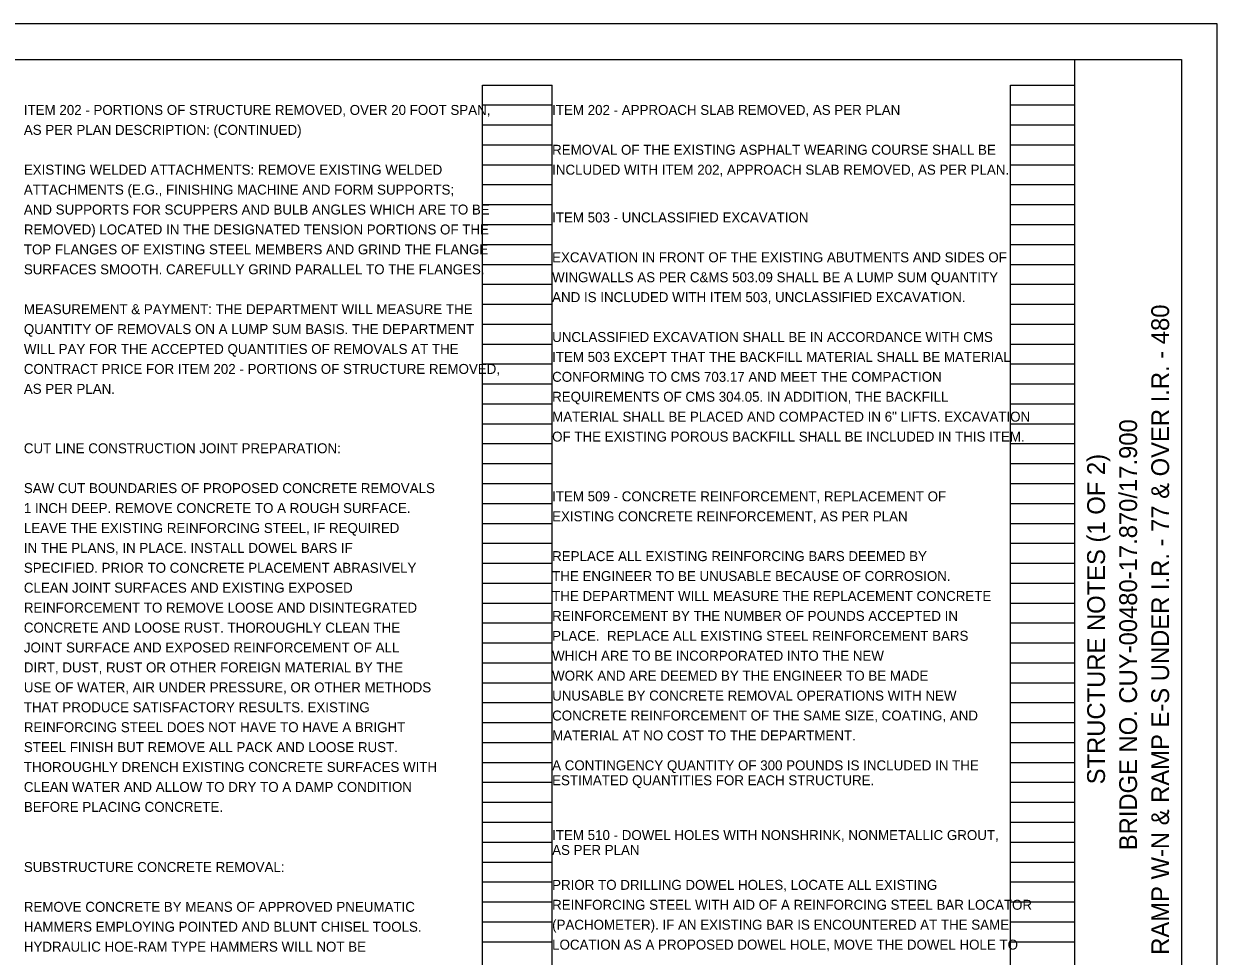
# Model space of a CAD drawing. Extents: x 0 to 34, y 0 to 22.
# Drawn here: x 17.24 to 34, y 8.9 to 22 of the extents above; entities that cross this region are included whole.
import ezdxf

# ---------------------------------------------------------------- set-up
doc = ezdxf.new("R2010")
doc.units = 0
for name, color, linetype in [('SH_Border', 7, 'Continuous'), ('SH_Cut_Line', 7, 'Continuous'), ('SH_Data', 7, 'Continuous'), ('SH_Text', 7, 'Continuous')]:
    doc.layers.add(name, color=color, linetype=linetype)

msp = doc.modelspace()

# ---------------------------------------------------------------- linework, layer by layer
at = {"layer": 'SH_Border'}
msp.add_line((32, 0.5), (32, 21.5), dxfattribs=at)
msp.add_lwpolyline([(1.5, 21.5), (33.5, 21.5), (33.5, 0.5), (1.5, 0.5)], close=True, dxfattribs=at)
at = {"layer": 'SH_Cut_Line'}
msp.add_lwpolyline([(0, 0), (34, 0), (34, 22), (0, 22)], close=True, dxfattribs=at)
at = {"layer": 'SH_Data'}
for p, q in [((23.68, 0.98), (23.68, 21.14)), ((23.68, 21.14), (24.66, 21.14)), ((24.66, 0.98), (24.66, 21.14)), ((31.1, 0.98), (31.1, 21.14)), ((31.1, 21.14), (32, 21.14)), ((32, 0.98), (32, 21.14)), ((23.68, 20.86), (24.66, 20.86)), ((31.1, 20.86), (32, 20.86)), ((23.68, 20.58), (24.66, 20.58)), ((31.1, 20.58), (32, 20.58)), ((23.68, 20.3), (24.66, 20.3)), ((31.1, 20.3), (32, 20.3)), ((23.68, 20.02), (24.66, 20.02)), ((31.1, 20.02), (32, 20.02)), ((23.68, 19.74), (24.66, 19.74)), ((31.1, 19.74), (32, 19.74)), ((23.68, 19.46), (24.66, 19.46)), ((31.1, 19.46), (32, 19.46)), ((23.68, 19.18), (24.66, 19.18)), ((31.1, 19.18), (32, 19.18)), ((23.68, 18.9), (24.66, 18.9)), ((31.1, 18.9), (32, 18.9)), ((23.68, 18.62), (24.66, 18.62)), ((31.1, 18.62), (32, 18.62)), ((23.68, 18.34), (24.66, 18.34)), ((31.1, 18.34), (32, 18.34)), ((23.68, 18.06), (24.66, 18.06)), ((31.1, 18.06), (32, 18.06)), ((23.68, 17.78), (24.66, 17.78)), ((31.1, 17.78), (32, 17.78)), ((23.68, 17.5), (24.66, 17.5)), ((31.1, 17.5), (32, 17.5)), ((23.68, 17.22), (24.66, 17.22)), ((31.1, 17.22), (32, 17.22)), ((23.68, 16.94), (24.66, 16.94)), ((31.1, 16.94), (32, 16.94)), ((23.68, 16.66), (24.66, 16.66)), ((31.1, 16.66), (32, 16.66)), ((23.68, 16.38), (24.66, 16.38)), ((31.1, 16.38), (32, 16.38)), ((23.68, 16.1), (24.66, 16.1)), ((31.1, 16.1), (32, 16.1)), ((23.68, 15.82), (24.66, 15.82)), ((31.1, 15.82), (32, 15.82)), ((23.68, 15.54), (24.66, 15.54)), ((31.1, 15.54), (32, 15.54)), ((23.68, 15.26), (24.66, 15.26)), ((31.1, 15.26), (32, 15.26)), ((23.68, 14.98), (24.66, 14.98)), ((31.1, 14.98), (32, 14.98)), ((23.68, 14.7), (24.66, 14.7)), ((31.1, 14.7), (32, 14.7)), ((23.68, 14.42), (24.66, 14.42)), ((31.1, 14.42), (32, 14.42)), ((23.68, 14.14), (24.66, 14.14)), ((31.1, 14.14), (32, 14.14)), ((23.68, 13.86), (24.66, 13.86)), ((31.1, 13.86), (32, 13.86)), ((23.68, 13.58), (24.66, 13.58)), ((31.1, 13.58), (32, 13.58)), ((23.68, 13.3), (24.66, 13.3)), ((31.1, 13.3), (32, 13.3)), ((23.68, 13.02), (24.66, 13.02)), ((31.1, 13.02), (32, 13.02)), ((23.68, 12.74), (24.66, 12.74)), ((31.1, 12.74), (32, 12.74)), ((23.68, 12.46), (24.66, 12.46)), ((31.1, 12.46), (32, 12.46)), ((23.68, 12.18), (24.66, 12.18)), ((31.1, 12.18), (32, 12.18)), ((23.68, 11.9), (24.66, 11.9)), ((31.1, 11.9), (32, 11.9)), ((23.68, 11.62), (24.66, 11.62)), ((31.1, 11.62), (32, 11.62)), ((23.68, 11.34), (24.66, 11.34)), ((31.1, 11.34), (32, 11.34)), ((23.68, 11.06), (24.66, 11.06)), ((31.1, 11.06), (32, 11.06)), ((23.68, 10.78), (24.66, 10.78)), ((31.1, 10.78), (32, 10.78)), ((23.68, 10.5), (24.66, 10.5)), ((31.1, 10.5), (32, 10.5)), ((23.68, 10.22), (24.66, 10.22)), ((31.1, 10.22), (32, 10.22)), ((23.68, 9.94), (24.66, 9.94)), ((31.1, 9.94), (32, 9.94)), ((23.68, 9.66), (24.66, 9.66)), ((31.1, 9.66), (32, 9.66)), ((23.68, 9.38), (24.66, 9.38)), ((31.1, 9.38), (32, 9.38)), ((23.68, 9.1), (24.66, 9.1)), ((31.1, 9.1), (32, 9.1))]:
    msp.add_line(p, q, dxfattribs=at)

# ---------------------------------------------------------------- texts
for s, p in [('RAMP W-N & RAMP E-S UNDER I.R. - 77 & OVER I.R. - 480', (33.325, 8.916)), ('BRIDGE NO. CUY-00480-17.870/17.900', (32.875, 10.385)), ('STRUCTURE NOTES (1 OF 2)', (32.425, 11.312))]:
    msp.add_text(s, height=0.25, rotation=90, dxfattribs=at).set_placement(p)
at = {"layer": 'SH_Text'}
for s, p in [('ITEM 202 - PORTIONS OF STRUCTURE REMOVED, OVER 20 FOOT SPAN,', (17.24, 20.72)), ('ITEM 202 - APPROACH SLAB REMOVED, AS PER PLAN', (24.66, 20.72)), ('AS PER PLAN DESCRIPTION: (CONTINUED)', (17.24, 20.44)), ('REMOVAL OF THE EXISTING ASPHALT WEARING COURSE SHALL BE', (24.66, 20.16)), ('EXISTING WELDED ATTACHMENTS: REMOVE EXISTING WELDED', (17.24, 19.88)), ('INCLUDED WITH ITEM 202, APPROACH SLAB REMOVED, AS PER PLAN.', (24.66, 19.88)), ('ATTACHMENTS (E.G., FINISHING MACHINE AND FORM SUPPORTS;', (17.24, 19.6)), ('AND SUPPORTS FOR SCUPPERS AND BULB ANGLES WHICH ARE TO BE', (17.24, 19.32)), ('ITEM 503 - UNCLASSIFIED EXCAVATION', (24.66, 19.209)), ('REMOVED) LOCATED IN THE DESIGNATED TENSION PORTIONS OF THE', (17.24, 19.04)), ('TOP FLANGES OF EXISTING STEEL MEMBERS AND GRIND THE FLANGE', (17.24, 18.76)), ('EXCAVATION IN FRONT OF THE EXISTING ABUTMENTS AND SIDES OF ', (24.66, 18.649)), ('SURFACES SMOOTH. CAREFULLY GRIND PARALLEL TO THE FLANGES.', (17.24, 18.48)), ('WINGWALLS AS PER C&MS 503.09 SHALL BE A LUMP SUM QUANTITY ', (24.66, 18.369)), ('AND IS INCLUDED WITH ITEM 503, UNCLASSIFIED EXCAVATION.', (24.66, 18.089)), ('MEASUREMENT & PAYMENT: THE DEPARTMENT WILL MEASURE THE', (17.24, 17.92)), ('QUANTITY OF REMOVALS ON A LUMP SUM BASIS. THE DEPARTMENT', (17.24, 17.64)), ('UNCLASSIFIED EXCAVATION SHALL BE IN ACCORDANCE WITH CMS ', (24.66, 17.529)), ('WILL PAY FOR THE ACCEPTED QUANTITIES OF REMOVALS AT THE', (17.24, 17.36)), ('ITEM 503 EXCEPT THAT THE BACKFILL MATERIAL SHALL BE MATERIAL ', (24.66, 17.249)), ('CONTRACT PRICE FOR ITEM 202 - PORTIONS OF STRUCTURE REMOVED,', (17.24, 17.08)), ('CONFORMING TO CMS 703.17 AND MEET THE COMPACTION ', (24.66, 16.969)), ('AS PER PLAN.', (17.24, 16.8)), ('REQUIREMENTS OF CMS 304.05. IN ADDITION, THE BACKFILL ', (24.66, 16.689)), ('MATERIAL SHALL BE PLACED AND COMPACTED IN 6" LIFTS. EXCAVATION ', (24.66, 16.409)), ('OF THE EXISTING POROUS BACKFILL SHALL BE INCLUDED IN THIS ITEM.', (24.66, 16.129)), ('CUT LINE CONSTRUCTION JOINT PREPARATION:', (17.24, 15.965)), ('SAW CUT BOUNDARIES OF PROPOSED CONCRETE REMOVALS', (17.24, 15.405)), ('ITEM 509 - CONCRETE REINFORCEMENT, REPLACEMENT OF', (24.66, 15.289)), ('1 INCH DEEP. REMOVE CONCRETE TO A ROUGH SURFACE.', (17.24, 15.125)), ('EXISTING CONCRETE REINFORCEMENT, AS PER PLAN', (24.66, 15.009)), ('LEAVE THE EXISTING REINFORCING STEEL, IF REQUIRED', (17.24, 14.845)), ('IN THE PLANS, IN PLACE. INSTALL DOWEL BARS IF', (17.24, 14.565)), ('REPLACE ALL EXISTING REINFORCING BARS DEEMED BY', (24.66, 14.449)), ('SPECIFIED. PRIOR TO CONCRETE PLACEMENT ABRASIVELY', (17.24, 14.285)), ('THE ENGINEER TO BE UNUSABLE BECAUSE OF CORROSION.', (24.66, 14.169)), ('CLEAN JOINT SURFACES AND EXISTING EXPOSED', (17.24, 14.005)), ('THE DEPARTMENT WILL MEASURE THE REPLACEMENT CONCRETE', (24.66, 13.889)), ('REINFORCEMENT TO REMOVE LOOSE AND DISINTEGRATED', (17.24, 13.725)), ('REINFORCEMENT BY THE NUMBER OF POUNDS ACCEPTED IN', (24.66, 13.609)), ('CONCRETE AND LOOSE RUST. THOROUGHLY CLEAN THE', (17.24, 13.445)), ('PLACE.  REPLACE ALL EXISTING STEEL REINFORCEMENT BARS', (24.66, 13.329)), ('JOINT SURFACE AND EXPOSED REINFORCEMENT OF ALL', (17.24, 13.165)), ('WHICH ARE TO BE INCORPORATED INTO THE NEW', (24.66, 13.049)), ('DIRT, DUST, RUST OR OTHER FOREIGN MATERIAL BY THE', (17.24, 12.885)), ('WORK AND ARE DEEMED BY THE ENGINEER TO BE MADE', (24.66, 12.769)), ('USE OF WATER, AIR UNDER PRESSURE, OR OTHER METHODS', (17.24, 12.605)), ('UNUSABLE BY CONCRETE REMOVAL OPERATIONS WITH NEW', (24.66, 12.489)), ('THAT PRODUCE SATISFACTORY RESULTS. EXISTING', (17.24, 12.325)), ('CONCRETE REINFORCEMENT OF THE SAME SIZE, COATING, AND', (24.66, 12.209)), ('REINFORCING STEEL DOES NOT HAVE TO HAVE A BRIGHT', (17.24, 12.045)), ('MATERIAL AT NO COST TO THE DEPARTMENT.', (24.66, 11.929)), ('STEEL FINISH BUT REMOVE ALL PACK AND LOOSE RUST.', (17.24, 11.765)), ('THOROUGHLY DRENCH EXISTING CONCRETE SURFACES WITH', (17.24, 11.485)), ('A CONTINGENCY QUANTITY OF 300 POUNDS IS INCLUDED IN THE', (24.66, 11.509)), ('ESTIMATED QUANTITIES FOR EACH STRUCTURE.', (24.66, 11.299)), ('CLEAN WATER AND ALLOW TO DRY TO A DAMP CONDITION', (17.24, 11.205)), ('BEFORE PLACING CONCRETE.', (17.24, 10.925)), ('ITEM 510 - DOWEL HOLES WITH NONSHRINK, NONMETALLIC GROUT, ', (24.66, 10.529)), ('AS PER PLAN', (24.66, 10.319)), ('SUBSTRUCTURE CONCRETE REMOVAL:', (17.24, 10.08)), ('PRIOR TO DRILLING DOWEL HOLES, LOCATE ALL EXISTING ', (24.66, 9.829)), ('REMOVE CONCRETE BY MEANS OF APPROVED PNEUMATIC', (17.24, 9.52)), ('REINFORCING STEEL WITH AID OF A REINFORCING STEEL BAR LOCATOR ', (24.66, 9.549)), ('(PACHOMETER). IF AN EXISTING BAR IS ENCOUNTERED AT THE SAME ', (24.66, 9.269)), ('HAMMERS EMPLOYING POINTED AND BLUNT CHISEL TOOLS.', (17.24, 9.24)), ('HYDRAULIC HOE-RAM TYPE HAMMERS WILL NOT BE', (17.24, 8.96)), ('LOCATION AS A PROPOSED DOWEL HOLE, MOVE THE DOWEL HOLE TO ', (24.66, 8.989))]:
    msp.add_text(s, height=0.14, dxfattribs=at).set_placement(p)

doc.saveas('drawing.dxf')
